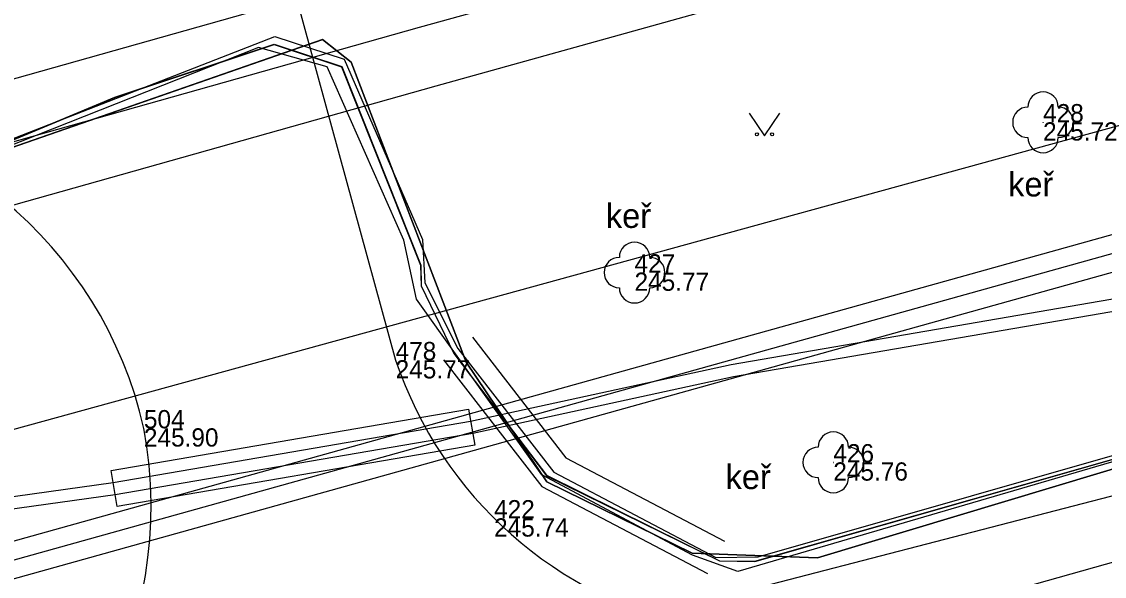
# Model space of a CAD drawing. Extents: x -599432 to -598680, y -1159407 to -1158632.
# Drawn here: x -599205.78 to -599187.97, y -1158937.48 to -1158928.37 of the extents above; entities that cross this region are included whole.
import ezdxf

# ---------------------------------------------------------------- set-up
doc = ezdxf.new("R2010")
doc.units = 0
for name, color, linetype in [('0004 VY - Body podrobné', 7, 'Continuous'), ('0005 VY - Body podrobné - čísla', 7, 'Continuous'), ('0006 VY - Body podrobné - výšky', 7, 'Continuous'), ('0030 ZA - Chodník', 7, 'Continuous'), ('0034 ZA - Kultury - značky', 7, 'Continuous'), ('0035 ZA - Strom - značka', 7, 'Continuous'), ('0036 TE - Strom - popis', 7, 'Continuous'), ('0202 PV - MUNI', 7, 'Continuous'), ('0203 PV - MUNI - chránička', 7, 'Continuous'), ('0206 PV - BVK - kanalizace - jednotná', 7, 'Continuous'), ('0211 PV - BVK - kanalizace - jednotná okraj', 7, 'Continuous'), ('0264 PV - TB - parovod mimo provoz', 7, 'Continuous'), ('0302 PV - RWE - NTL', 7, 'Continuous'), ('0308 PV - RWE - ochranné pásmo', 7, 'Continuous'), ('0354 PV - EON - VN', 7, 'Continuous'), ('0359 PV - EON - sdělovací kabely', 7, 'Continuous'), ('0367 PV - EON - VN chránička', 7, 'Continuous'), ('0407 PV - TSB - kabelové vedení přibližný zákres', 7, 'Continuous'), ('0454 PV - O2 - kabel zaměřený', 7, 'Continuous'), ('0530 PV - T-mobile - optické kabely', 7, 'Continuous'), ('0703 PV - DIAL TELECOM optický kabel', 7, 'Continuous'), ('0704 PV - ČD - kabely', 7, 'Continuous')]:
    doc.layers.add(name, color=color, linetype=linetype)

msp = doc.modelspace()

# ---------------------------------------------------------------- linework, layer by layer
at = {"layer": '0004 VY - Body podrobné'}
for p, q in [((-599188.98, -1158930.02), (-599188.98, -1158930.02)), ((-599195.7, -1158932.49), (-599195.7, -1158932.49)), ((-599199.63, -1158933.93), (-599199.63, -1158933.93)), ((-599203.77, -1158935.05), (-599203.77, -1158935.05)), ((-599192.43, -1158935.61), (-599192.43, -1158935.61)), ((-599198.01, -1158936.53), (-599198.01, -1158936.53))]:
    msp.add_line(p, q, dxfattribs=at)
at = {"layer": '0030 ZA - Chodník'}
for p, q in [((-599202.3, -1158924.18), (-599199.63, -1158933.93)), ((-599169.23, -1158932.02), (-599192.553, -1158938.578))]:
    msp.add_line(p, q, dxfattribs=at)
for centre, radius, start, end in [((-599210.404, -1158936.551), 6.801, 12.7459, 163.9487), ((-599193.307, -1158931.795), 6.673, 198.657, 258.3053), ((-599210.608, -1158936.326), 6.956, 212.5663, 10.5691)]:
    msp.add_arc(centre, radius, start, end, dxfattribs=at)
at = {"layer": '0034 ZA - Kultury - značky'}
msp.add_lwpolyline([(-599193.812, -1158929.867), (-599193.562, -1158930.242), (-599193.312, -1158929.867)], dxfattribs=at)
for centre in [(-599193.687, -1158930.217), (-599193.437, -1158930.217)]:
    msp.add_circle(centre, 0.025, dxfattribs=at)
at = {"layer": '0035 ZA - Strom - značka'}
for centre in [(-599188.98, -1158930.02), (-599195.7, -1158932.49), (-599192.43, -1158935.61)]:
    msp.add_circle(centre, 0.00025, dxfattribs=at)
for centre, start, end in [((-599188.98, -1158929.77), 0, 180), ((-599189.23, -1158930.02), 90, 270), ((-599188.73, -1158930.02), 270, 90), ((-599188.98, -1158930.27), 180, 360), ((-599195.7, -1158932.24), 0, 180), ((-599195.95, -1158932.49), 90, 270), ((-599195.45, -1158932.49), 270, 90), ((-599195.7, -1158932.74), 180, 360), ((-599192.43, -1158935.36), 0, 180), ((-599192.68, -1158935.61), 90, 270), ((-599192.18, -1158935.61), 270, 90), ((-599192.43, -1158935.86), 180, 360)]:
    msp.add_arc(centre, 0.25, start, end, dxfattribs=at)
at = {"layer": '0202 PV - MUNI'}
msp.add_lwpolyline([(-599255.365, -1158936.128), (-599252.9, -1158935.879), (-599249.514, -1158936.12), (-599229.166, -1158928.515), (-599221.329, -1158925.93), (-599220.289, -1158926.362), (-599218.079, -1158932.75), (-599214.197, -1158932.926), (-599209.818, -1158931.805), (-599201.617, -1158928.611), (-599200.477, -1158928.983), (-599199.188, -1158931.945), (-599199.148, -1158932.658), (-599198.604, -1158933.738), (-599197.027, -1158935.771), (-599194.361, -1158937.172), (-599193.665, -1158937.164), (-599183.138, -1158934.154), (-599174.357, -1158932.265), (-599146.637, -1158922.988), (-599125.848, -1158917.745)], dxfattribs=at)
at = {"layer": '0203 PV - MUNI - chránička'}
for points in [[(-599198.367, -1158933.554), (-599196.83, -1158935.536), (-599194.222, -1158936.907)], [(-599198.841, -1158933.922), (-599197.224, -1158936.007), (-599194.501, -1158937.438)]]:
    msp.add_lwpolyline(points, dxfattribs=at)
at = {"layer": '0206 PV - BVK - kanalizace - jednotná'}
msp.add_line((-599214.704, -1158939.667), (-599158.607, -1158924.017), dxfattribs=at)
at = {"layer": '0211 PV - BVK - kanalizace - jednotná okraj'}
for p, q in [((-599214.784, -1158939.378), (-599158.687, -1158923.729)), ((-599158.526, -1158924.306), (-599214.623, -1158939.956))]:
    msp.add_line(p, q, dxfattribs=at)
at = {"layer": '0264 PV - TB - parovod mimo provoz'}
msp.add_lwpolyline([(-599164.247, -1158923.62), (-599240.684, -1158944.621), (-599259.43, -1158878.076)], dxfattribs=at)
at = {"layer": '0302 PV - RWE - NTL'}
msp.add_lwpolyline([(-599042.76, -1158885.49), (-599068.42, -1158892.17), (-599094.54, -1158899.36), (-599103.01, -1158901.75), (-599109.28, -1158903.4), (-599121.29, -1158906.57), (-599128.03, -1158908.44), (-599139.52, -1158911.687), (-599140.38, -1158911.93), (-599166.16, -1158919.18), (-599194.33, -1158927.1), (-599199.24, -1158928.46), (-599225.65, -1158935.9)], dxfattribs=at)
at = {"layer": '0308 PV - RWE - ochranné pásmo'}
msp.add_lwpolyline([(-599140.109, -1158912.892), (-599165.889, -1158920.143), (-599194.061, -1158928.063), (-599198.971, -1158929.423), (-599225.379, -1158936.863), (-599225.777, -1158936.975), (-599226.5, -1158936.57), (-599226.613, -1158936.171), (-599226.725, -1158935.773), (-599226.32, -1158935.05), (-599225.921, -1158934.937), (-599199.509, -1158927.497), (-599194.599, -1158926.137), (-599166.431, -1158918.217), (-599140.651, -1158910.968)], dxfattribs=at)
at = {"layer": '0354 PV - EON - VN'}
for points in [[(-599227.006, -1158917.879), (-599226.226, -1158920.627), (-599225.016, -1158925.127), (-599223.393, -1158930.87), (-599222.954, -1158931.602), (-599220.922, -1158932.906), (-599216.548, -1158935.368), (-599214.474, -1158936.465), (-599212.649, -1158936.84), (-599208.772, -1158936.77), (-599204.245, -1158936.139), (-599198.361, -1158935.128), (-599194.071, -1158934.198), (-599187.146, -1158933.007)], [(-599226.814, -1158917.821), (-599226.034, -1158920.573), (-599224.824, -1158925.073), (-599223.207, -1158930.79), (-599222.806, -1158931.458), (-599220.818, -1158932.734), (-599216.452, -1158935.192), (-599214.406, -1158936.275), (-599212.631, -1158936.64), (-599208.788, -1158936.57), (-599204.275, -1158935.941), (-599198.399, -1158934.932), (-599194.109, -1158934.002), (-599187.194, -1158932.813)]]:
    msp.add_lwpolyline(points, dxfattribs=at)
at = {"layer": '0359 PV - EON - sdělovací kabely'}
msp.add_lwpolyline([(-599279.16, -1158962.47), (-599254.08, -1158955.38), (-599253.49, -1158954.94), (-599253.3, -1158954.3), (-599252.93, -1158950.8), (-599250.35, -1158946.57), (-599249.33, -1158946.19), (-599247.7, -1158945.87), (-599212.14, -1158935.06), (-599209.49, -1158932.25), (-599207.11, -1158930.84), (-599200.83, -1158928.66), (-599200.36, -1158929.03), (-599198.47, -1158933.96), (-599197.14, -1158935.93), (-599194.75, -1158937.1), (-599192.69, -1158937.18), (-599181.15, -1158933.71), (-599175.84, -1158932.87), (-599169.02, -1158930.6), (-599153, -1158925.67), (-599136.91, -1158920.86)], dxfattribs=at)
msp.add_lwpolyline([(-599279.16, -1158962.47), (-599254.08, -1158955.38), (-599253.49, -1158954.94), (-599253.3, -1158954.3), (-599252.93, -1158950.8), (-599250.35, -1158946.57), (-599249.33, -1158946.19), (-599247.7, -1158945.87), (-599212.14, -1158935.06), (-599209.49, -1158932.25), (-599207.11, -1158930.84), (-599200.83, -1158928.66), (-599200.36, -1158929.03), (-599198.47, -1158933.96), (-599197.14, -1158935.93), (-599194.75, -1158937.1), (-599192.69, -1158937.18), (-599181.15, -1158933.71), (-599175.84, -1158932.87), (-599169.02, -1158930.6), (-599153, -1158925.67), (-599136.91, -1158920.86)], dxfattribs=at)
at = {"layer": '0367 PV - EON - VN chránička'}
for p, q in [((-599204.311, -1158935.744), (-599198.431, -1158934.734)), ((-599198.431, -1158934.734), (-599198.329, -1158935.326)), ((-599198.329, -1158935.326), (-599204.209, -1158936.336)), ((-599204.209, -1158936.336), (-599204.311, -1158935.744))]:
    msp.add_line(p, q, dxfattribs=at)
at = {"layer": '0407 PV - TSB - kabelové vedení přibližný zákres'}
msp.add_line((-599193.921, -1158937.733), (-599179.236, -1158933.931), dxfattribs=at)
at = {"layer": '0454 PV - O2 - kabel zaměřený'}
for points in [[(-599214.12, -1158932.98), (-599209.84, -1158931.94), (-599204.25, -1158929.61), (-599201.63, -1158928.74), (-599200.52, -1158929.11), (-599199.22, -1158932.37), (-599199.21, -1158932.71), (-599198.67, -1158933.82), (-599197.15, -1158935.83), (-599194.3, -1158937.23), (-599193.72, -1158937.24), (-599183.02, -1158934.19), (-599174.44, -1158932.29), (-599146.63, -1158923.2), (-599137.96, -1158921.08)], [(-599198.67, -1158933.82), (-599197.15, -1158935.83), (-599194.3, -1158937.23)]]:
    msp.add_lwpolyline(points, dxfattribs=at)
at = {"layer": '0530 PV - T-mobile - optické kabely'}
for points in [[(-599207.11, -1158930.839), (-599200.829, -1158928.66)], [(-599200.829, -1158928.66), (-599200.36, -1158929.03)], [(-599204.25, -1158929.608), (-599201.628, -1158928.734)], [(-599201.628, -1158928.734), (-599200.516, -1158929.104)], [(-599200.516, -1158929.104), (-599199.217, -1158932.367)], [(-599200.36, -1158929.03), (-599198.47, -1158933.96)], [(-599209.842, -1158931.938), (-599204.25, -1158929.608)], [(-599199.217, -1158932.367), (-599199.208, -1158932.71)], [(-599199.208, -1158932.71), (-599198.67, -1158933.818)], [(-599198.67, -1158933.818), (-599197.149, -1158935.822)], [(-599192.689, -1158937.18), (-599181.149, -1158933.709)], [(-599198.47, -1158933.96), (-599197.14, -1158935.929)], [(-599193.721, -1158937.235), (-599183.016, -1158934.185)], [(-599197.149, -1158935.822), (-599194.3, -1158937.227)], [(-599197.14, -1158935.929), (-599194.75, -1158937.1)], [(-599194.75, -1158937.1), (-599192.689, -1158937.18)], [(-599194.3, -1158937.227), (-599193.721, -1158937.235)]]:
    msp.add_lwpolyline(points, dxfattribs=at)
at = {"layer": '0703 PV - DIAL TELECOM optický kabel'}
msp.add_lwpolyline([(-599061.55, -1158893.87), (-599061.24, -1158895.32), (-599061.95, -1158898.88), (-599063.86, -1158900.66), (-599074.72, -1158903.34), (-599088.3, -1158908.08), (-599104.33, -1158911.91), (-599119.51, -1158916.31), (-599136.91, -1158920.86), (-599153, -1158925.67), (-599169.02, -1158930.6), (-599175.84, -1158932.87), (-599181.15, -1158933.71), (-599192.69, -1158937.18), (-599194.75, -1158937.1), (-599197.14, -1158935.93), (-599198.47, -1158933.96), (-599200.36, -1158929.03), (-599200.83, -1158928.66), (-599207.11, -1158930.84)], dxfattribs=at)
at = {"layer": '0704 PV - ČD - kabely'}
msp.add_lwpolyline([(-599114.022, -1158914.733), (-599146.63, -1158923.02), (-599155.536, -1158926.021), (-599174.713, -1158932.481), (-599184.127, -1158934.514), (-599194.001, -1158937.403), (-599194.747, -1158937.133), (-599197.224, -1158935.816), (-599199.288, -1158932.926), (-599199.494, -1158931.958), (-599200.756, -1158929.108), (-599201.883, -1158928.791), (-599209.995, -1158931.998), (-599214.441, -1158933.077), (-599217.743, -1158932.664), (-599219.108, -1158931.045), (-599220.314, -1158926.664), (-599221.203, -1158926.41), (-599249.842, -1158936.887), (-599252.604, -1158936.443), (-599255.248, -1158936.617)], dxfattribs=at)

# ---------------------------------------------------------------- texts
at = {"layer": '0005 VY - Body podrobné - čísla'}
for s, p in [('428', (-599188.98, -1158930.02)), ('427', (-599195.7, -1158932.49)), ('478', (-599199.63, -1158933.93)), ('504', (-599203.77, -1158935.05)), ('426', (-599192.43, -1158935.61)), ('422', (-599198.01, -1158936.53))]:
    msp.add_text(s, height=0.3, dxfattribs=at).set_placement(p)
at = {"layer": '0006 VY - Body podrobné - výšky'}
for s, p in [('245.72', (-599188.98, -1158930.32)), ('245.77', (-599195.7, -1158932.79)), ('245.77', (-599199.63, -1158934.23)), ('245.90', (-599203.77, -1158935.35)), ('245.76', (-599192.43, -1158935.91)), ('245.74', (-599198.01, -1158936.83))]:
    msp.add_text(s, height=0.3, dxfattribs=at).set_placement(p)
at = {"layer": '0036 TE - Strom - popis'}
for p in [(-599189.554, -1158931.239), (-599196.171, -1158931.756), (-599194.202, -1158936.049)]:
    msp.add_text('keř', height=0.4, dxfattribs=at).set_placement(p)

doc.saveas('drawing.dxf')
